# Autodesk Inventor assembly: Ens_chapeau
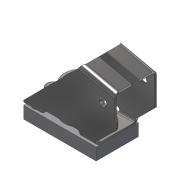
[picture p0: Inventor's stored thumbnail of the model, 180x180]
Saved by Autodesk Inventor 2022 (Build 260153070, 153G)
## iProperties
Created: 2018-06
Part Number: Ens_chapeau
Material: Générique
Document SubType Name: Assembly
Designer: Fabian Perrée
Mass: 105.136 g
Surface Area: 173.547 cm^2
Volume: 19.7524 cm^3
Density: 5.32267 g/cm^3
Author: Fabian Perrée
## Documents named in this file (5)
- C:\Users\Fabian\Google Drive\01_Giup\01_Clients\07_ENI\Manuscrit\Fichiers_exercice\Capteur\Ens_chapeau\Ens_chapeau.iam
- C:\Users\Fabian\Google Drive\01_Giup\01_Clients\07_ENI\Manuscrit\Fichiers_exercice\Capteur\Ens_chapeau\Composants\Chapeau_capteur.ipt
- C:\Users\Fabian\Google Drive\01_Giup\01_Clients\07_ENI\Manuscrit\Fichiers_exercice\Capteur\Ens_chapeau\Composants\Bille_18.ipt
- C:\Users\Fabian\Google Drive\01_Giup\01_Clients\07_ENI\Manuscrit\Fichiers_exercice\Capteur\Ens_levier\Composants\Etrier_tole.ipt
- C:\Users\Fabian\Google Drive\01_Giup\01_Clients\07_ENI\Manuscrit\Fichiers_exercice\CC\fr-FR\ISO 4762(2)\ISO 4762 - M5 x 8ISO.ipt
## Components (5 placed, 4 different names)
1. Etrier_tole:1 — Logement:3, Logement:4
2. Chapeau_capteur:1 — Logement:3, Logement:4
3. Bille_18:1
4. ISO 4762 M5 x 8:1
5. ISO 4762 M5 x 8:2
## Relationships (2: Insert 2)
- Logement:3 [Insert]: Etrier_tole:1 ↔ Chapeau_capteur:1
- Logement:4 [Insert]: Etrier_tole:1 ↔ Chapeau_capteur:1
